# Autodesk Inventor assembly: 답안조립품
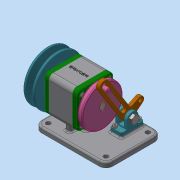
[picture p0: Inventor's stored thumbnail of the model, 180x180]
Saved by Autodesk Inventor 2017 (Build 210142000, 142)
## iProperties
Part Number: 답안조립품
Material: 일반
Document SubType Name: Assembly
Designer: mrc
Author: mrc
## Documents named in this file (19)
- C:\Users\mrc\Desktop\601106V1040\답안조립품.iam
- C:\Users\mrc\Desktop\601106V1040\본체.ipt
- C:\Users\mrc\Desktop\601106V1040\V-벨트풀리.ipt
- C:\Users\mrc\Desktop\601106V1040\너트 M8.ipt
- C:\Users\mrc\Desktop\601106V1040\너트 M10x1.ipt
- C:\Users\mrc\Desktop\601106V1040\돌림판.ipt
- C:\Users\mrc\Desktop\601106V1040\멈춤나사 M3x5.ipt
- C:\Users\mrc\Desktop\601106V1040\베어링 6004.ipt
- C:\Users\mrc\Desktop\601106V1040\볼트 M4.ipt
- C:\Users\mrc\Desktop\601106V1040\오일 실 17 30 5.ipt
- C:\Users\mrc\Desktop\601106V1040\와셔 8x15.5.ipt
- C:\Users\mrc\Desktop\601106V1040\축.ipt
- C:\Users\mrc\Desktop\601106V1040\커버.ipt
- C:\Users\mrc\Desktop\601106V1040\크랭크.ipt
- C:\Users\mrc\Desktop\601106V1040\키 4 x 4 x 8.ipt
- C:\Users\mrc\Desktop\601106V1040\키 5 x 5 x 12.ipt
- C:\Users\mrc\Desktop\601106V1040\핀 3 x 8.ipt
- C:\Users\mrc\Desktop\601106V1040\힌지 축.ipt
- C:\Users\mrc\Desktop\601106V1040\힌지.ipt
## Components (3 placed, 2 different names)
1. V-벨트풀리:1
2. 핀 3 x 8:1 — 플러쉬:1
3. 핀 3 x 8:2 — 플러쉬:2
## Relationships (2: Flush 2)
- 플러쉬:1 [Flush]: 핀 3 x 8:1
- 플러쉬:2 [Flush]: 핀 3 x 8:2
